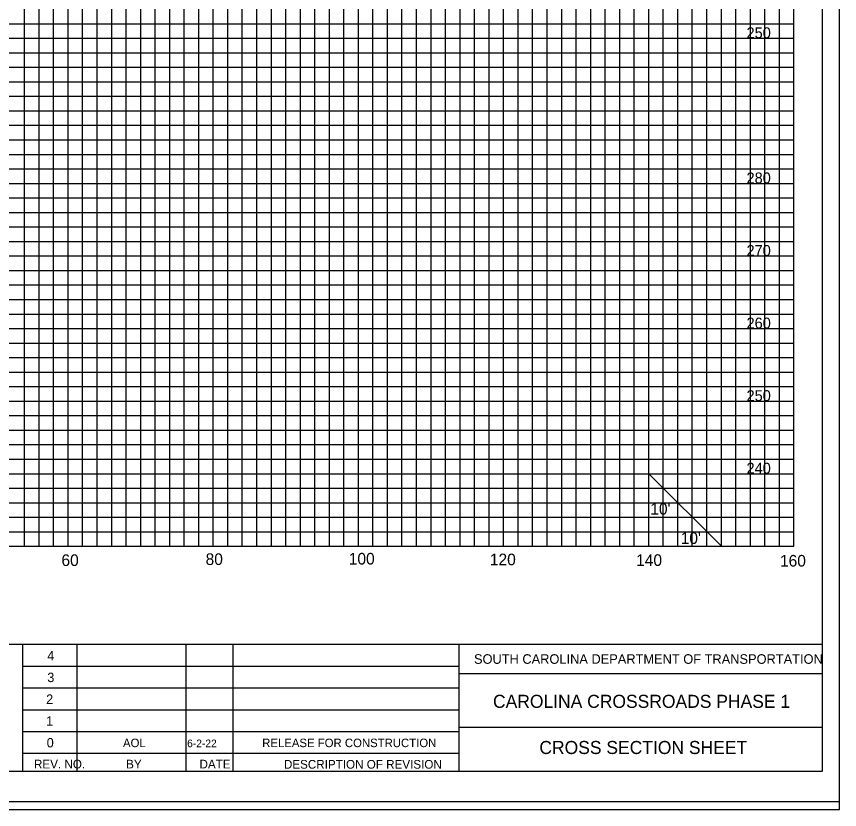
# Model space of a CAD drawing. Extents: x 967 to 1746, y 964 to 7904.
# Drawn here: x 1212.9 to 1326.3, y 5163.7 to 5273 of the extents above; entities that cross this region are included whole.
import ezdxf

# ---------------------------------------------------------------- set-up
doc = ezdxf.new("R2010")
doc.units = 0
for name, color, linetype in [('Default', 7, 'Continuous'), ('RD_SHT_Bndy', 7, 'Continuous'), ('RD_SHT_IplotShp', 7, 'Continuous'), ('RD_SHT_Misc1', 7, 'Continuous'), ('RD_SHT_MjGrid', 7, 'Continuous'), ('RD_SHT_MnGrid', 7, 'Continuous'), ('RD_SHT_TX', 7, 'Continuous'), ('RD_Sketch1', 7, 'Continuous')]:
    doc.layers.add(name, color=color, linetype=linetype)

msp = doc.modelspace()

# ---------------------------------------------------------------- linework, layer by layer
at = {"layer": 'RD_SHT_Bndy'}
for p, q in [((1323.89, 5378.46), (1323.89, 5168.98)), ((996.11, 5186.49), (1323.89, 5186.49)), ((1213.76, 5168.94), (1213.76, 5186.49)), ((1221.26, 5168.95), (1221.26, 5186.48)), ((1236.26, 5168.95), (1236.26, 5186.48)), ((1242.76, 5168.95), (1242.76, 5186.48)), ((1273.88, 5168.98), (1273.88, 5186.49)), ((1213.76, 5183.48), (1273.88, 5183.48)), ((1323.93, 5182.43), (1273.88, 5182.43)), ((1213.76, 5180.48), (1273.88, 5180.48)), ((1213.76, 5177.48), (1273.88, 5177.48)), ((1323.89, 5175.04), (1273.88, 5175.04)), ((1213.76, 5174.48), (1273.88, 5174.48)), ((1213.76, 5171.48), (1273.88, 5171.48)), ((1323.89, 5168.98), (996.11, 5168.98))]:
    msp.add_line(p, q, dxfattribs=at)
at = {"layer": 'RD_SHT_IplotShp'}
for points in [[(967.41, 5163.72), (1326.28, 5163.72), (1326.28, 5383.72), (967.41, 5383.72)], [(988.52, 5164.84), (1326.28, 5164.84), (1326.28, 5382.6), (988.52, 5382.6)]]:
    msp.add_lwpolyline(points, close=True, dxfattribs=at)
at = {"layer": 'RD_SHT_MjGrid'}
for p, q in [((1220, 5200), (1220, 5370)), ((1230, 5200), (1230, 5370)), ((1240, 5200), (1240, 5370)), ((1250, 5200), (1250, 5370)), ((1260, 5200), (1260, 5370)), ((1270, 5200), (1270, 5370)), ((1280, 5200), (1280, 5370)), ((1290, 5200), (1290, 5370)), ((1300, 5200), (1300, 5370)), ((1310, 5200), (1310, 5370)), ((1320, 5200), (1320, 5370)), ((1000, 5270), (1320, 5270)), ((1000, 5260), (1320, 5260)), ((1000, 5250), (1320, 5250)), ((1000, 5240), (1320, 5240)), ((1000, 5230), (1320, 5230)), ((1000, 5220), (1320, 5220)), ((1000, 5210), (1320, 5210)), ((1000, 5200), (1320, 5200))]:
    msp.add_line(p, q, dxfattribs=at)
at = {"layer": 'RD_SHT_MnGrid'}
for p, q in [((1214, 5200), (1214, 5370)), ((1216, 5200), (1216, 5370)), ((1218, 5200), (1218, 5370)), ((1222, 5200), (1222, 5370)), ((1224, 5200), (1224, 5370)), ((1226, 5200), (1226, 5370)), ((1228, 5200), (1228, 5370)), ((1232, 5200), (1232, 5370)), ((1234, 5200), (1234, 5370)), ((1236, 5200), (1236, 5370)), ((1238, 5200), (1238, 5370)), ((1242, 5200), (1242, 5370)), ((1244, 5200), (1244, 5370)), ((1246, 5200), (1246, 5370)), ((1248, 5200), (1248, 5370)), ((1252, 5200), (1252, 5370)), ((1254, 5200), (1254, 5370)), ((1256, 5200), (1256, 5370)), ((1258, 5200), (1258, 5370)), ((1262, 5200), (1262, 5370)), ((1264, 5200), (1264, 5370)), ((1266, 5200), (1266, 5370)), ((1268, 5200), (1268, 5370)), ((1272, 5200), (1272, 5370)), ((1274, 5200), (1274, 5370)), ((1276, 5200), (1276, 5370)), ((1278, 5200), (1278, 5370)), ((1282, 5200), (1282, 5370)), ((1284, 5200), (1284, 5370)), ((1286, 5200), (1286, 5370)), ((1288, 5200), (1288, 5370)), ((1292, 5200), (1292, 5370)), ((1294, 5200), (1294, 5370)), ((1296, 5200), (1296, 5370)), ((1298, 5200), (1298, 5370)), ((1302, 5200), (1302, 5370)), ((1304, 5200), (1304, 5370)), ((1306, 5200), (1306, 5370)), ((1308, 5200), (1308, 5370)), ((1312, 5200), (1312, 5370)), ((1314, 5200), (1314, 5370)), ((1316, 5200), (1316, 5370)), ((1318, 5200), (1318, 5370)), ((1000, 5272), (1320, 5272)), ((1000, 5268), (1320, 5268)), ((1000, 5266), (1320, 5266)), ((1000, 5264), (1320, 5264)), ((1000, 5262), (1320, 5262)), ((1000, 5258), (1320, 5258)), ((1000, 5256), (1320, 5256)), ((1000, 5254), (1320, 5254)), ((1000, 5252), (1320, 5252)), ((1000, 5248), (1320, 5248)), ((1000, 5246), (1320, 5246)), ((1000, 5244), (1320, 5244)), ((1000, 5242), (1320, 5242)), ((1000, 5238), (1320, 5238)), ((1000, 5236), (1320, 5236)), ((1000, 5234), (1320, 5234)), ((1000, 5232), (1320, 5232)), ((1000, 5228), (1320, 5228)), ((1000, 5226), (1320, 5226)), ((1000, 5224), (1320, 5224)), ((1000, 5222), (1320, 5222)), ((1000, 5218), (1320, 5218)), ((1000, 5216), (1320, 5216)), ((1000, 5214), (1320, 5214)), ((1000, 5212), (1320, 5212)), ((1000, 5208), (1320, 5208)), ((1000, 5206), (1320, 5206)), ((1000, 5204), (1320, 5204)), ((1000, 5202), (1320, 5202))]:
    msp.add_line(p, q, dxfattribs=at)
at = {"layer": 'RD_SHT_TX'}
msp.add_line((1300, 5210), (1310, 5200), dxfattribs=at)
at = {"layer": 'RD_Sketch1'}
msp.add_lwpolyline([(967.41, 5163.72), (1326.28, 5163.72), (1326.28, 5383.72), (967.41, 5383.72)], close=True, dxfattribs=at)

# ---------------------------------------------------------------- texts
at = {"layer": 'Default'}
for s, p in [('250', (1313.47, 5270)), ('280', (1313.47, 5250)), ('270', (1313.47, 5240)), ('260', (1313.47, 5230)), ('250', (1313.47, 5220)), ('240', (1313.47, 5210))]:
    msp.add_text(s, height=1.5, dxfattribs=at).set_placement(p)
at = {"layer": 'RD_SHT_Misc1'}
for s, height, p in [('AOL', 1.17, (1227.56, 5172.32)), ('RELEASE FOR CONSTRUCTION', 1.17, (1246.74, 5172.32)), ('6-2-22', 1.053, (1236.4, 5172.31))]:
    msp.add_text(s, height=height, dxfattribs=at).set_placement(p)
at = {"layer": 'RD_SHT_TX'}
for s, height, p in [("10'", 1.6, (1300.21, 5204.36)), ("10'", 1.6, (1304.4, 5200.32)), ('60', 1.6, (1219.08, 5197.28)), ('80', 1.6, (1238.94, 5197.42)), ('100', 1.6, (1258.67, 5197.48)), ('120', 1.6, (1278.11, 5197.38)), ('140', 1.6, (1298.26, 5197.29)), ('160', 1.6, (1318.08, 5197.2)), ('4', 1.3, (1217.13, 5184.28)), ('SOUTH CAROLINA DEPARTMENT OF TRANSPORTATION', 1.32, (1275.92, 5183.8)), ('3', 1.3, (1217.13, 5181.28)), ('2', 1.3, (1216.97, 5178.28)), ('1', 1.3, (1216.97, 5175.28)), ('0', 1.3, (1217.05, 5172.28)), ('REV. NO.', 1.2, (1215.3, 5169.38)), ('BY', 1.2, (1227.99, 5169.38)), ('DATE', 1.2, (1238.1, 5169.38)), ('DESCRIPTION OF REVISION', 1.2, (1249.73, 5169.35))]:
    msp.add_text(s, height=height, dxfattribs=at).set_placement(p)
for s, p in [('CAROLINA CROSSROADS PHASE 1', (1278.54, 5177.73)), ('CROSS SECTION SHEET', (1284.93, 5171.37))]:
    msp.add_text(s, height=1.8, rotation=0, dxfattribs=at).set_placement(p)

doc.saveas('drawing.dxf')
